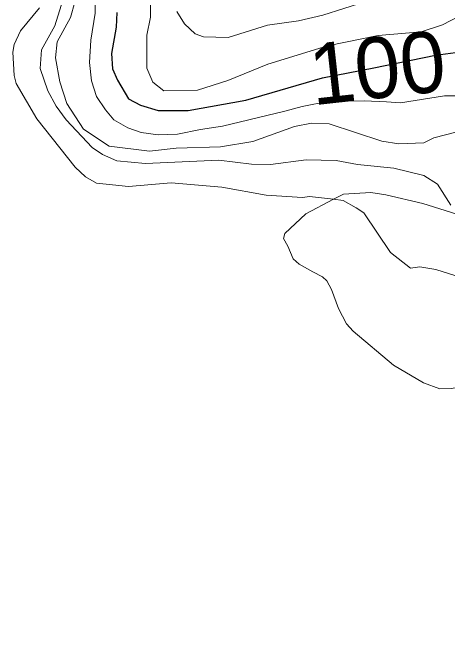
# Model space of a CAD drawing. Extents: x 474.5 to 500, y 7345.7 to 7373.4.
# Drawn here: x 484.113 to 484.682, y 7365.995 to 7366.839 of the extents above; entities that cross this region are included whole.
import ezdxf
from ezdxf.enums import TextEntityAlignment as Align

# ---------------------------------------------------------------- set-up
doc = ezdxf.new("R2010")
doc.units = 0
doc.header["$LTSCALE"] = 0.032
doc.linetypes.add('SHORT_DASHED', pattern=[2.7, 1.5, -1.2])
for name, color, linetype, lineweight in [('1', 7, 'Continuous', 25), ('16', 7, 'SHORT_DASHED', 13), ('2', 7, 'Continuous', 13)]:
    doc.layers.add(name, color=color, linetype=linetype, lineweight=lineweight)
doc.layers.add('61', color=7, linetype='Continuous')

msp = doc.modelspace()

# ---------------------------------------------------------------- linework, layer by layer
at = {"layer": '1'}
msp.add_lwpolyline([(484.2493, 7366.8394), (484.2484, 7366.82), (484.2421, 7366.7855), (484.2437, 7366.7654), (484.2499, 7366.7504), (484.2647, 7366.726), (484.2803, 7366.7179), (484.3035, 7366.711), (484.3425, 7366.711), (484.4183, 7366.7245), (484.5189, 7366.7538), (484.5863, 7366.7666), (484.6672, 7366.7832), (484.7193, 7366.7905)], dxfattribs=at)
at = {"layer": '16'}
for points in [[(484.713, 7366.5694), (484.6504, 7366.5891), (484.6019, 7366.6004), (484.5823, 7366.6035), (484.5463, 7366.6014), (484.5331, 7366.5945)], [(484.5331, 7366.5945), (484.4968, 7366.5756), (484.4695, 7366.5496), (484.4679, 7366.5433), (484.4736, 7366.5331), (484.4805, 7366.5164), (484.4883, 7366.5095), (484.506, 7366.4997), (484.5188, 7366.4928), (484.5247, 7366.4879), (484.5307, 7366.4763), (484.5398, 7366.4515), (484.5505, 7366.4313), (484.5591, 7366.4218), (484.6119, 7366.3773), (484.6512, 7366.3541), (484.6728, 7366.3462)], [(484.6728, 7366.3462), (484.6881, 7366.3465), (484.7212, 7366.3532), (484.7494, 7366.3673), (484.771, 7366.3841)]]:
    msp.add_lwpolyline(points, dxfattribs=at)
at = {"layer": '2'}
for points in [[(484.2939, 7366.8984), (484.2932, 7366.8333), (484.2884, 7366.8094), (484.2884, 7366.7661), (484.2962, 7366.7479), (484.311, 7366.7366), (484.3548, 7366.7374), (484.3947, 7366.7501), (484.4471, 7366.7716), (484.5255, 7366.7954), (484.5917, 7366.8091), (484.6482, 7366.8137), (484.6762, 7366.8231), (484.7071, 7366.8394)], [(484.1782, 7366.8554), (484.1679, 7366.8219), (484.1504, 7366.7902), (484.1488, 7366.7658), (484.1588, 7366.7364), (484.1696, 7366.7163), (484.1827, 7366.6985), (484.2168, 7366.6624), (484.2304, 7366.6531), (484.2493, 7366.6451), (484.2869, 7366.6416), (484.3829, 7366.6456), (484.4257, 7366.6404), (484.4508, 7366.6401), (484.4976, 7366.6463), (484.5367, 7366.6455), (484.5646, 7366.6401), (484.6125, 7366.6353), (484.6516, 7366.6255), (484.6696, 7366.6144), (484.6873, 7366.5867)], [(484.1941, 7366.8526), (484.1885, 7366.8328), (484.171, 7366.8009), (484.1687, 7366.7797), (484.1743, 7366.7483), (484.1837, 7366.72), (484.2053, 7366.6864), (484.239, 7366.664), (484.2922, 7366.6576), (484.3268, 7366.6615), (484.3849, 7366.6633), (484.4276, 7366.6703), (484.482, 7366.6899), (484.5043, 7366.6942), (484.5274, 7366.6933), (484.5966, 7366.6705), (484.619, 7366.6673), (484.6519, 7366.6686), (484.6646, 7366.6751), (484.6956, 7366.683)], [(484.2207, 7366.8518), (484.2207, 7366.8384), (484.2153, 7366.8029), (484.2135, 7366.7738), (484.2158, 7366.7495), (484.2225, 7366.7293), (484.2342, 7366.7118), (484.2454, 7366.6984), (484.2634, 7366.688), (484.2813, 7366.6822), (484.3033, 7366.6791), (484.3289, 7366.68), (484.3589, 7366.6858), (484.3877, 7366.6903), (484.4222, 7366.6988), (484.4693, 7366.71), (484.4922, 7366.7159), (484.5277, 7366.723), (484.5735, 7366.7235), (484.6026, 7366.7221), (484.6209, 7366.7207), (484.6787, 7366.7302), (484.7117, 7366.7302)], [(484.3277, 7366.8405), (484.3377, 7366.8242), (484.352, 7366.8114), (484.3628, 7366.8075), (484.3951, 7366.8066), (484.4469, 7366.8226), (484.4875, 7366.8283), (484.5192, 7366.8355), (484.5745, 7366.853)], [(484.5731, 7366.5769), (484.5631, 7366.5835), (484.5458, 7366.5929), (484.5331, 7366.5945), (484.5019, 7366.5984), (484.4924, 7366.597), (484.4449, 7366.6), (484.3867, 7366.6104), (484.3205, 7366.616), (484.2644, 7366.6113), (484.2227, 7366.6155), (484.208, 7366.6239), (484.1946, 7366.6365), (484.1443, 7366.7001), (484.1173, 7366.7463), (484.1144, 7366.7567), (484.1129, 7366.7871), (484.1148, 7366.7973), (484.1231, 7366.8153), (484.1479, 7366.8453)], [(485.0733, 7365.9923), (485.0814, 7366.0148), (485.0845, 7366.0372), (485.0789, 7366.0818), (485.0612, 7366.1377), (485.0245, 7366.2159), (485.0037, 7366.2501), (484.975, 7366.2724), (484.9356, 7366.2984), (484.8351, 7366.3527), (484.771, 7366.3841), (484.7446, 7366.397), (484.7345, 7366.4008), (484.7297, 7366.4022), (484.7096, 7366.4194), (484.7013, 7366.4264), (484.6993, 7366.436), (484.7056, 7366.4635), (484.6937, 7366.4944), (484.6675, 7366.5027), (484.6465, 7366.5059), (484.6341, 7366.5044), (484.6078, 7366.5248), (484.5731, 7366.5769)]]:
    msp.add_lwpolyline(points, dxfattribs=at)

# ---------------------------------------------------------------- texts
at = {"layer": '61'}
msp.add_text('100', height=0.08, rotation=6.277, dxfattribs=at).set_placement((484.59508, 7366.7273), align=Align.CENTER)

doc.saveas('drawing.dxf')
